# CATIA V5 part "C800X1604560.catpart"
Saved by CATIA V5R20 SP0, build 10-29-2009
Part number: C800X1604560
Source: Unknown
Property "A": "70"
Property "ARTICLENO": "C800X1604560"
Property "B": "32"
Property "BOMINFO": "C800X1604560"
Property "C": "120"
Property "CA": "C800X1604560"
Property "D1": "120"
Property "DES": "ROTATING EYEBOLT WITH RING Ton 16,0 M45x60"
Property "E": "112"
Property "H": "262"
Property "L": "60"
Property "LINA": "C800X1604560"
Property "NB": "C800X1604560"
Property "NBSYN": "$CODE."
Property "NN": "C800X"
Property "NT": "Rotating eyebolt with ring"
Property "SIZE": "M45"
Property "SUPPLIER": "CF"
Property "SW": "100"
Property "WEIGHT": "10900"
Property "WLL": "16.00"
Bounding box of the stored display mesh (mm): x -67 to 67, y -60 to 293.813, z -60 to 60
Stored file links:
  C:\Users\Utente\Desktop\3D files 800X\C800X1604560.catpart
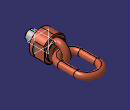
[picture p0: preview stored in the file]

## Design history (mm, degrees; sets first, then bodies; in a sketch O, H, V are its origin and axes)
Body1 "Geometry.1" (main body)
  Solid1 "C800X1604560.catpart": solid without history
